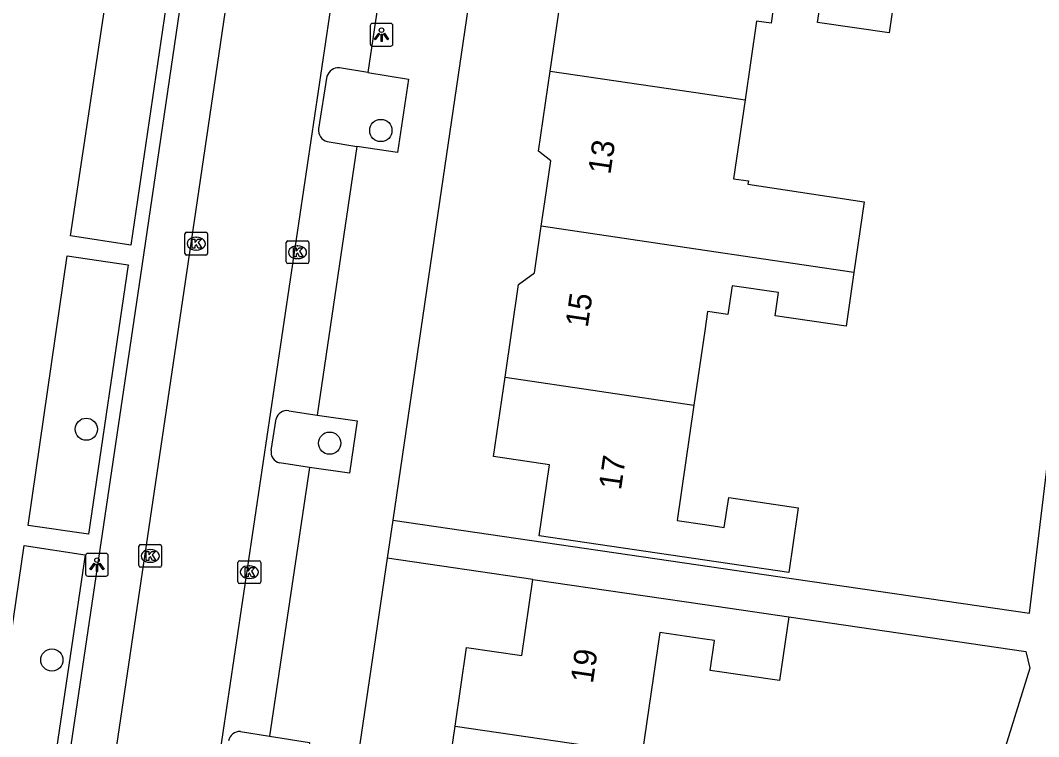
# Model space of a CAD drawing. Extents: x 159280 to 160375, y 384531 to 385872.
# Drawn here: x 159969.86 to 160014.71, y 384726.45 to 384757.99 of the extents above; entities that cross this region are included whole.
import ezdxf

# ---------------------------------------------------------------- set-up
doc = ezdxf.new("R2010")
doc.units = 0
for name, color, linetype in [('IMGEO_Boom', 7, 'Continuous'), ('IMGEO_Kolk', 7, 'Continuous'), ('IMGEO_Lichtpunt', 7, 'Continuous'), ('IMGEO_Pand', 7, 'Continuous'), ('IMGEO_Pand_nummerreeks', 7, 'Continuous'), ('IMGEO_Parkeervlak_open', 7, 'Continuous'), ('IMGEO_Rijbaan_lokaal_open', 7, 'Continuous'), ('IMGEO_Voetpad_open', 7, 'Continuous')]:
    doc.layers.add(name, color=color, linetype=linetype)

msp = doc.modelspace()

# ---------------------------------------------------------------- linework, layer by layer
at = {"layer": 'IMGEO_Boom'}
for centre in [(159985.735, 384753.142), (159972.763, 384739.985), (159983.478, 384739.37), (159971.247, 384729.821)]:
    msp.add_circle(centre, 0.489, dxfattribs=at)
at = {"layer": 'IMGEO_Kolk'}
for p, q in [((159977.105, 384747.732), (159977.105, 384748.584)), ((159977.18, 384748.658), (159978.032, 384748.658)), ((159978.106, 384748.584), (159978.106, 384747.732)), ((159977.593, 384748.438), (159977.618, 384748.438)), ((159981.566, 384747.352), (159981.566, 384748.204)), ((159981.641, 384748.278), (159982.493, 384748.278)), ((159982.567, 384748.204), (159982.567, 384747.352)), ((159978.032, 384747.658), (159977.18, 384747.658)), ((159977.616, 384747.878), (159977.591, 384747.878)), ((159982.054, 384748.058), (159982.079, 384748.058)), ((159982.493, 384747.278), (159981.641, 384747.278)), ((159982.077, 384747.498), (159982.052, 384747.498)), ((159975.08, 384733.977), (159975.08, 384734.829)), ((159975.155, 384734.903), (159976.007, 384734.903)), ((159975.568, 384734.683), (159975.593, 384734.683)), ((159976.081, 384734.829), (159976.081, 384733.977)), ((159979.518, 384734.189), (159980.37, 384734.189)), ((159976.007, 384733.903), (159975.155, 384733.903)), ((159975.591, 384734.123), (159975.566, 384734.123)), ((159979.443, 384733.263), (159979.443, 384734.115)), ((159979.931, 384733.969), (159979.956, 384733.969)), ((159980.444, 384734.115), (159980.444, 384733.263)), ((159979.954, 384733.409), (159979.929, 384733.409)), ((159980.37, 384733.189), (159979.518, 384733.189))]:
    msp.add_line(p, q, dxfattribs=at)
for points in [[(159977.105, 384747.732), (159977.105, 384748.584)], [(159977.18, 384748.658), (159978.032, 384748.658)], [(159978.106, 384748.584), (159978.106, 384747.732)], [(159977.426, 384748.358), (159977.549, 384748.358), (159977.549, 384748.207), (159977.679, 384748.358), (159977.843, 384748.358), (159977.697, 384748.207), (159977.85, 384747.958), (159977.698, 384747.958), (159977.613, 384748.122), (159977.549, 384748.055), (159977.549, 384747.958), (159977.426, 384747.958), (159977.426, 384748.358)], [(159981.566, 384747.352), (159981.566, 384748.204)], [(159981.641, 384748.278), (159982.493, 384748.278)], [(159982.567, 384748.204), (159982.567, 384747.352)], [(159978.032, 384747.658), (159977.18, 384747.658)], [(159981.887, 384747.978), (159982.01, 384747.978), (159982.01, 384747.827), (159982.14, 384747.978), (159982.304, 384747.978), (159982.158, 384747.827), (159982.311, 384747.578), (159982.159, 384747.578), (159982.074, 384747.742), (159982.01, 384747.675), (159982.01, 384747.578), (159981.887, 384747.578), (159981.887, 384747.978)], [(159982.493, 384747.278), (159981.641, 384747.278)], [(159975.08, 384733.977), (159975.08, 384734.829)], [(159975.155, 384734.903), (159976.007, 384734.903)], [(159976.081, 384734.829), (159976.081, 384733.977)], [(159975.401, 384734.603), (159975.524, 384734.603), (159975.524, 384734.452), (159975.654, 384734.603), (159975.818, 384734.603), (159975.672, 384734.452), (159975.825, 384734.203), (159975.673, 384734.203), (159975.588, 384734.367), (159975.524, 384734.3), (159975.524, 384734.203), (159975.401, 384734.203), (159975.401, 384734.603)], [(159979.518, 384734.189), (159980.37, 384734.189)], [(159976.007, 384733.903), (159975.155, 384733.903)], [(159979.443, 384733.263), (159979.443, 384734.115)], [(159979.764, 384733.889), (159979.887, 384733.889), (159979.887, 384733.738), (159980.017, 384733.889), (159980.181, 384733.889), (159980.035, 384733.738), (159980.188, 384733.489), (159980.036, 384733.489), (159979.951, 384733.653), (159979.887, 384733.586), (159979.887, 384733.489), (159979.764, 384733.489), (159979.764, 384733.889)], [(159980.444, 384734.115), (159980.444, 384733.263)], [(159980.37, 384733.189), (159979.518, 384733.189)]]:
    msp.add_lwpolyline(points, dxfattribs=at)
for centre, start, end in [((159977.182, 384748.582), 91.552, 178.448), ((159977.182, 384748.582), 91.552, 178.448), ((159978.03, 384748.582), 1.552, 88.448), ((159978.03, 384748.582), 1.552, 88.448), ((159981.643, 384748.202), 91.552, 178.448), ((159981.643, 384748.202), 91.552, 178.448), ((159982.491, 384748.202), 1.552, 88.448), ((159982.491, 384748.202), 1.552, 88.448), ((159977.182, 384747.734), 181.552, 268.448), ((159977.182, 384747.734), 181.552, 268.448), ((159978.03, 384747.734), 271.552, 358.448), ((159978.03, 384747.734), 271.552, 358.448), ((159981.643, 384747.354), 181.552, 268.448), ((159981.643, 384747.354), 181.552, 268.448), ((159982.491, 384747.354), 271.552, 358.448), ((159982.491, 384747.354), 271.552, 358.448), ((159975.157, 384734.827), 91.552, 178.448), ((159975.157, 384734.827), 91.552, 178.448), ((159976.005, 384734.827), 1.552, 88.448), ((159976.005, 384734.827), 1.552, 88.448), ((159979.52, 384734.113), 91.552, 178.448), ((159979.52, 384734.113), 91.552, 178.448), ((159980.368, 384734.113), 1.552, 88.448), ((159980.368, 384734.113), 1.552, 88.448), ((159975.157, 384733.979), 181.552, 268.448), ((159975.157, 384733.979), 181.552, 268.448), ((159976.005, 384733.979), 271.552, 358.448), ((159976.005, 384733.979), 271.552, 358.448), ((159979.52, 384733.265), 181.552, 268.448), ((159979.52, 384733.265), 181.552, 268.448), ((159980.368, 384733.265), 271.552, 358.448), ((159980.368, 384733.265), 271.552, 358.448)]:
    msp.add_arc(centre, 0.0765, start, end, dxfattribs=at)
for centre, major_axis, ratio, start_param, end_param in [((159977.592, 384748.158), (-0.387, 0.002), 0.722429, 4.712389, 7.853982), ((159977.617, 384748.158), (-0.39, 0.002), 0.717154, 1.570796, 4.712389), ((159982.053, 384747.778), (-0.387, 0.002), 0.722429, 4.712389, 7.853982), ((159982.078, 384747.778), (-0.39, 0.002), 0.717154, 1.570796, 4.712389), ((159975.567, 384734.403), (-0.387, 0.002), 0.722429, 4.712389, 7.853982), ((159975.592, 384734.403), (-0.39, 0.002), 0.717154, 1.570796, 4.712389), ((159979.93, 384733.689), (-0.387, 0.002), 0.722429, 4.712389, 7.853982), ((159979.955, 384733.689), (-0.39, 0.002), 0.717154, 1.570796, 4.712389)]:
    msp.add_ellipse(centre, major_axis=major_axis, ratio=ratio, start_param=start_param, end_param=end_param, dxfattribs=at)
at = {"layer": 'IMGEO_Lichtpunt'}
for p, q in [((159985.268, 384757.763), (159985.268, 384756.956)), ((159985.268, 384757.763), (159985.268, 384756.956)), ((159986.17, 384757.858), (159985.362, 384757.858)), ((159986.17, 384757.858), (159985.362, 384757.858)), ((159986.264, 384756.956), (159986.264, 384757.763)), ((159986.264, 384756.956), (159986.264, 384757.763)), ((159985.362, 384756.862), (159986.17, 384756.862)), ((159985.362, 384756.862), (159986.17, 384756.862)), ((159972.735, 384734.42), (159972.735, 384733.613)), ((159972.735, 384734.42), (159972.735, 384733.613)), ((159973.637, 384734.515), (159972.829, 384734.515)), ((159973.637, 384734.515), (159972.829, 384734.515)), ((159973.731, 384733.613), (159973.731, 384734.42)), ((159973.731, 384733.613), (159973.731, 384734.42)), ((159972.829, 384733.519), (159973.637, 384733.519)), ((159972.829, 384733.519), (159973.637, 384733.519))]:
    msp.add_line(p, q, dxfattribs=at)
for points in [[(159985.642, 384757.427), (159985.681, 384757.399), (159985.493, 384757.137), (159985.455, 384757.164), (159985.642, 384757.427)], [(159985.744, 384757.379), (159985.791, 384757.379), (159985.791, 384757.057), (159985.744, 384757.057), (159985.744, 384757.379)], [(159985.854, 384757.399), (159985.892, 384757.426), (159986.079, 384757.164), (159986.04, 384757.136), (159985.854, 384757.399)], [(159973.109, 384734.084), (159973.148, 384734.056), (159972.96, 384733.794), (159972.922, 384733.821), (159973.109, 384734.084)], [(159973.211, 384734.036), (159973.258, 384734.036), (159973.258, 384733.714), (159973.211, 384733.714), (159973.211, 384734.036)], [(159973.321, 384734.056), (159973.359, 384734.083), (159973.546, 384733.821), (159973.507, 384733.793), (159973.321, 384734.056)]]:
    msp.add_lwpolyline(points, dxfattribs=at)
for centre in [(159985.767, 384757.561), (159973.234, 384734.218)]:
    msp.add_circle(centre, 0.0994, dxfattribs=at)
for centre, start, end in [((159985.362, 384757.763), 90, 180), ((159985.362, 384757.763), 90, 180), ((159986.17, 384757.763), 0, 90), ((159986.17, 384757.763), 0, 90), ((159985.362, 384756.956), 180, 270), ((159985.362, 384756.956), 180, 270), ((159986.17, 384756.956), 270, 0), ((159986.17, 384756.956), 270, 360), ((159972.829, 384734.42), 90, 180), ((159972.829, 384734.42), 90, 180), ((159973.637, 384734.42), 0, 90), ((159973.637, 384734.42), 0, 90), ((159972.829, 384733.613), 180, 270), ((159972.829, 384733.613), 180, 270), ((159973.637, 384733.613), 270, 0), ((159973.637, 384733.613), 270, 360)]:
    msp.add_arc(centre, 0.0946, start, end, dxfattribs=at)
at = {"layer": 'IMGEO_Pand'}
for points in [[(159993.194, 384755.754), (159993.677, 384759.064), (159994.419, 384759.617), (159994.825, 384762.4)], [(160008.549, 384760.378), (160008.121, 384757.443), (160004.974, 384757.902), (160005.113, 384758.859), (160003.109, 384759.152), (160002.922, 384757.869), (160002.286, 384757.962), (160001.779, 384754.489)], [(159992.798, 384748.925), (159992.955, 384750), (159993.219, 384751.811), (159992.681, 384752.236), (159993.194, 384755.754)], [(159993.194, 384755.754), (160000, 384754.751), (160001.779, 384754.489)], [(160001.779, 384754.489), (160001.273, 384751.017), (160001.925, 384750.922), (160001.904, 384750.776), (160007.024, 384750), (160006.571, 384746.895)], [(159991.209, 384742.272), (159991.806, 384746.361), (159992.5, 384746.878), (159992.798, 384748.925)], [(160006.571, 384746.895), (160000, 384747.863), (159992.798, 384748.925)], [(160006.571, 384746.895), (160006.225, 384744.52), (160003.104, 384744.975), (160003.255, 384746.007), (160001.208, 384746.305), (160001.024, 384745.04), (160000.125, 384745.171), (160000, 384744.314), (159999.524, 384741.047)], [(159999.524, 384741.047), (159998.783, 384735.966), (160000, 384735.788), (160000.863, 384735.662), (160001.055, 384736.973), (160004.117, 384736.526), (160004.085, 384736.311), (160003.701, 384733.68), (159992.707, 384735.285), (159993.165, 384738.422), (159990.7, 384738.781), (159991.209, 384742.272)], [(159991.209, 384742.272), (159999.524, 384741.047)], [(159989.003, 384726.902), (159989.51, 384730.374), (159991.941, 384730.02), (159992.43, 384733.369)], [(159992.43, 384733.369), (159997.378, 384732.647), (160000, 384732.265), (160003.706, 384731.724)], [(160003.706, 384731.724), (160003.297, 384728.916), (160000.233, 384729.363), (160000.424, 384730.674), (160000, 384730.736), (159998.017, 384731.025), (159997.24, 384725.699)], [(159988.646, 384720.109), (159988.962, 384722.277), (159988.432, 384722.987), (159989.003, 384726.902)], [(159989.003, 384726.902), (159997.24, 384725.699)]]:
    msp.add_lwpolyline(points, dxfattribs=at)
at = {"layer": 'IMGEO_Parkeervlak_open'}
for points in [[(159985.169, 384755.7), (159983.909, 384755.909)], [(159983.359, 384755.531), (159982.997, 384753.217)], [(159983.379, 384752.654), (159984.685, 384752.434)], [(159981.677, 384740.799), (159982.927, 384740.61)], [(159980.911, 384739.053), (159981.123, 384740.442)], [(159982.599, 384738.292), (159981.278, 384738.511)], [(159979.551, 384726.67), (159980.832, 384726.461)]]:
    msp.add_lwpolyline(points, dxfattribs=at)
for centre, radius, start, end in [((159983.892, 384755.344), 0.565, 88.3091, 160.6903), ((159983.52, 384753.161), 0.526, 173.8538, 254.4606), ((159981.606, 384740.301), 0.503, 81.838, 163.7578), ((159981.351, 384738.956), 0.451, 167.5654, 260.6402), ((159979.527, 384726.158), 0.513, 87.3435, 168.3914)]:
    msp.add_arc(centre, radius, start, end, dxfattribs=at)
at = {"layer": 'IMGEO_Rijbaan_lokaal_open'}
for points in [[(159989.688, 384799.82), (159989.119, 384796.166), (159974.741, 384699.469)], [(159968.822, 384690.463), (159977.186, 384746.875), (159982.002, 384779.548)]]:
    msp.add_lwpolyline(points, dxfattribs=at)
at = {"layer": 'IMGEO_Voetpad_open'}
for points in [[(159986.258, 384735.984), (160003.921, 384733.4), (160014.299, 384731.886), (160015.76, 384743.962), (160020.308, 384781.549), (160021.355, 384784.522), (160035.962, 384806.663), (160044.571, 384819.713), (160029.19, 384829.86)], [(159996.464, 384802.013), (159995.827, 384801.045), (159988.319, 384750), (159986.258, 384735.984)], [(159968.38, 384690.986), (159966.912, 384691.202), (159975.227, 384747.165), (159979.813, 384778.452), (159979.939, 384779.353), (159981.474, 384779.125)], [(159986.048, 384761.643), (159985.169, 384755.7)], [(159973.78, 384759.96), (159976.418, 384759.586), (159974.731, 384748.093), (159972.061, 384748.507), (159973.78, 384759.96)], [(159985.169, 384755.7), (159986.958, 384755.403), (159986.468, 384752.177), (159984.685, 384752.434)], [(159984.685, 384752.434), (159982.927, 384740.61)], [(159971.918, 384747.622), (159974.607, 384747.232), (159972.865, 384735.361), (159970.202, 384735.745), (159971.918, 384747.622)], [(159982.927, 384740.61), (159984.699, 384740.353), (159984.349, 384738.056), (159982.599, 384738.292)], [(159982.599, 384738.292), (159980.832, 384726.461)], [(159986.258, 384735.984), (159986.011, 384734.306)], [(159970.029, 384734.861), (159972.719, 384734.456), (159971.396, 384725.531), (159968.717, 384725.98), (159970.029, 384734.861)], [(159986.011, 384734.306), (159979.512, 384690.12)], [(159992.43, 384733.369), (159986.011, 384734.306)], [(160003.706, 384731.724), (160014.148, 384730.2), (160014.315, 384729.455), (160012.16, 384722.524), (160010.366, 384717.15), (160008.046, 384709.688), (160006.275, 384703.947), (160005.914, 384704.059), (160003.497, 384696.526), (160002.619, 384693.786)], [(159980.832, 384726.461), (159982.589, 384726.184), (159982.574, 384726.065), (159981.973, 384721.921), (159980.184, 384722.184)]]:
    msp.add_lwpolyline(points, dxfattribs=at)

# ---------------------------------------------------------------- texts
at = {"layer": 'IMGEO_Pand_nummerreeks'}
for s, rotation, p in [('13', 81.5773, (159995.843, 384751.174)), ('15', 81.5773, (159994.845, 384744.434)), ('17', 81.7095, (159996.312, 384737.275)), ('19', 81.6936, (159995.072, 384728.757))]:
    msp.add_text(s, height=1, rotation=rotation, dxfattribs=at).set_placement(p)

doc.saveas('drawing.dxf')
